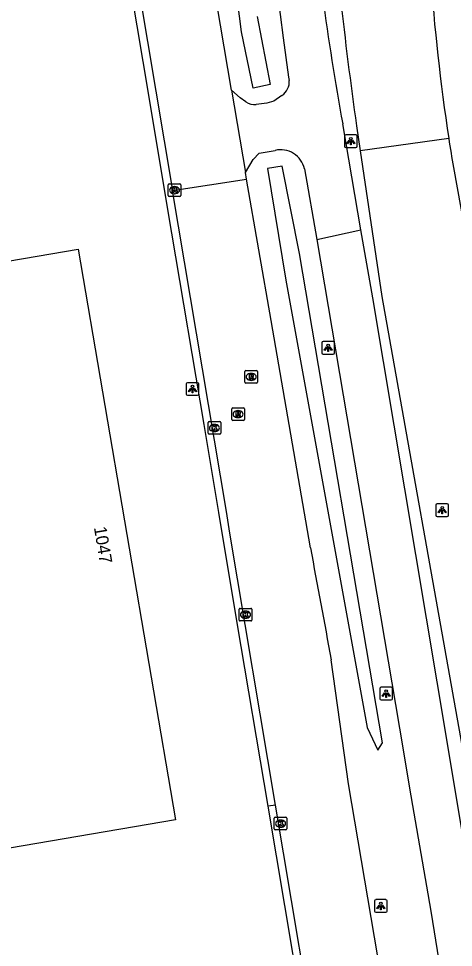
# Model space of a CAD drawing. Extents: x 154324 to 155743, y 382939 to 384183.
# Drawn here: x 154996.5 to 155031, y 383695.9 to 383769.7 of the extents above; entities that cross this region are included whole.
import ezdxf

# ---------------------------------------------------------------- set-up
doc = ezdxf.new("R2010")
doc.units = 0
for name, color, linetype in [('IMGEO_Fietspad_gesloten', 7, 'Continuous'), ('IMGEO_Kolk', 7, 'Continuous'), ('IMGEO_Lichtpunt', 7, 'Continuous'), ('IMGEO_Pand', 7, 'Continuous'), ('IMGEO_Pand_nummerreeks', 7, 'Continuous'), ('IMGEO_Rijbaan_lokaal_gesloten', 7, 'Continuous'), ('IMGEO_Rijbaan_lokaal_open', 7, 'Continuous'), ('IMGEO_Rijbaan_regionaal_gesloten', 7, 'Continuous'), ('IMGEO_Rioolput', 7, 'Continuous'), ('IMGEO_Waterloop', 7, 'Continuous')]:
    doc.layers.add(name, color=color, linetype=linetype)

msp = doc.modelspace()

# ---------------------------------------------------------------- linework, layer by layer
at = {"layer": 'IMGEO_Fietspad_gesloten'}
for points in [[(155016.997, 383771.855), (155017.48, 383768.134), (155017.908, 383765.009), (155017.961, 383764.734)], [(155014.521, 383763.048), (155014.065, 383763.349), (155013.373, 383763.974)], [(155017.375, 383763.556), (155016.736, 383763.085), (155016.191, 383762.943), (155015.337, 383762.826)], [(155023.65, 383752.887), (155022.201, 383761.283)], [(155014.481, 383757.434), (155015.084, 383758.454), (155015.579, 383758.975), (155016.83, 383759.18)], [(155019.156, 383757.716), (155020.155, 383752.117)], [(155020.155, 383752.117), (155023.65, 383752.887)], [(155069.375, 383489.212), (155067.803, 383490.288), (155064.93, 383506.848), (155055.586, 383562.322), (155035.787, 383680.446), (155030.556, 383711.937), (155024.582, 383747.491), (155023.65, 383752.887)], [(155020.155, 383752.117), (155027.003, 383711.594), (155027.513, 383708.543), (155029.197, 383698.769), (155030.596, 383690.066), (155052.123, 383561.719), (155057.1, 383532.805), (155064.796, 383488.095)]]:
    msp.add_lwpolyline(points, dxfattribs=at)
for centre, radius, start, end in [((155254.724, 383803.119), 236.257, 185.24892, 190.19973), ((155016.686, 383764.634), 1.279, 302.60576, 4.49784), ((155015.195, 383763.915), 1.098, 232.13028, 277.43079), ((155017.293, 383757.336), 1.902, 11.54173, 104.0851)]:
    msp.add_arc(centre, radius, start, end, dxfattribs=at)
at = {"layer": 'IMGEO_Kolk'}
for p, q in [((155008.354, 383755.604), (155008.354, 383756.456)), ((155008.429, 383756.53), (155009.281, 383756.53)), ((155008.842, 383756.31), (155008.867, 383756.31)), ((155009.355, 383756.456), (155009.355, 383755.604)), ((155009.281, 383755.53), (155008.429, 383755.53)), ((155008.865, 383755.75), (155008.84, 383755.75)), ((155011.514, 383736.723), (155011.514, 383737.575)), ((155011.589, 383737.649), (155012.441, 383737.649)), ((155012.515, 383737.575), (155012.515, 383736.723)), ((155012.025, 383736.869), (155012, 383736.869)), ((155012.002, 383737.429), (155012.027, 383737.429)), ((155012.441, 383736.649), (155011.589, 383736.649)), ((155014.061, 383722.823), (155014.913, 383722.823)), ((155013.986, 383721.897), (155013.986, 383722.749)), ((155014.474, 383722.603), (155014.499, 383722.603)), ((155014.987, 383722.749), (155014.987, 383721.897)), ((155014.913, 383721.823), (155014.061, 383721.823)), ((155014.497, 383722.043), (155014.472, 383722.043)), ((155016.771, 383705.306), (155016.771, 383706.158)), ((155016.846, 383706.232), (155017.698, 383706.232)), ((155017.259, 383706.012), (155017.284, 383706.012)), ((155017.772, 383706.158), (155017.772, 383705.306)), ((155017.698, 383705.232), (155016.846, 383705.232)), ((155017.282, 383705.452), (155017.257, 383705.452))]:
    msp.add_line(p, q, dxfattribs=at)
for points in [[(155008.354, 383755.604), (155008.354, 383756.456)], [(155008.429, 383756.53), (155009.281, 383756.53)], [(155008.675, 383756.23), (155008.798, 383756.23), (155008.798, 383756.079), (155008.928, 383756.23), (155009.092, 383756.23), (155008.946, 383756.079), (155009.099, 383755.83), (155008.947, 383755.83), (155008.862, 383755.994), (155008.798, 383755.927), (155008.798, 383755.83), (155008.675, 383755.83), (155008.675, 383756.23)], [(155009.355, 383756.456), (155009.355, 383755.604)], [(155009.281, 383755.53), (155008.429, 383755.53)], [(155011.514, 383736.723), (155011.514, 383737.575)], [(155011.589, 383737.649), (155012.441, 383737.649)], [(155012.515, 383737.575), (155012.515, 383736.723)], [(155011.835, 383737.349), (155011.958, 383737.349), (155011.958, 383737.198), (155012.088, 383737.349), (155012.252, 383737.349), (155012.106, 383737.198), (155012.259, 383736.949), (155012.107, 383736.949), (155012.022, 383737.113), (155011.958, 383737.046), (155011.958, 383736.949), (155011.835, 383736.949), (155011.835, 383737.349)], [(155012.441, 383736.649), (155011.589, 383736.649)], [(155014.061, 383722.823), (155014.913, 383722.823)], [(155013.986, 383721.897), (155013.986, 383722.749)], [(155014.307, 383722.523), (155014.43, 383722.523), (155014.43, 383722.372), (155014.56, 383722.523), (155014.724, 383722.523), (155014.578, 383722.372), (155014.731, 383722.123), (155014.579, 383722.123), (155014.494, 383722.287), (155014.43, 383722.22), (155014.43, 383722.123), (155014.307, 383722.123), (155014.307, 383722.523)], [(155014.987, 383722.749), (155014.987, 383721.897)], [(155014.913, 383721.823), (155014.061, 383721.823)], [(155016.771, 383705.306), (155016.771, 383706.158)], [(155016.846, 383706.232), (155017.698, 383706.232)], [(155017.092, 383705.932), (155017.215, 383705.932), (155017.215, 383705.781), (155017.345, 383705.932), (155017.509, 383705.932), (155017.363, 383705.781), (155017.516, 383705.532), (155017.364, 383705.532), (155017.279, 383705.696), (155017.215, 383705.629), (155017.215, 383705.532), (155017.092, 383705.532), (155017.092, 383705.932)], [(155017.772, 383706.158), (155017.772, 383705.306)], [(155017.698, 383705.232), (155016.846, 383705.232)]]:
    msp.add_lwpolyline(points, dxfattribs=at)
for centre, start, end in [((155008.431, 383756.454), 91.55205, 178.44795), ((155008.431, 383756.454), 91.55205, 178.44795), ((155009.279, 383756.454), 1.55205, 88.44795), ((155009.279, 383756.454), 1.55205, 88.44795), ((155008.431, 383755.606), 181.55205, 268.44795), ((155008.431, 383755.606), 181.55205, 268.44795), ((155009.279, 383755.606), 271.55205, 358.44795), ((155009.279, 383755.606), 271.55205, 358.44795), ((155011.591, 383737.573), 91.55205, 178.44795), ((155011.591, 383737.573), 91.55205, 178.44795), ((155012.439, 383737.573), 1.55205, 88.44795), ((155012.439, 383737.573), 1.55205, 88.44795), ((155011.591, 383736.725), 181.55205, 268.44795), ((155011.591, 383736.725), 181.55205, 268.44795), ((155012.439, 383736.725), 271.55205, 358.44795), ((155012.439, 383736.725), 271.55205, 358.44795), ((155014.063, 383722.747), 91.55205, 178.44795), ((155014.063, 383722.747), 91.55205, 178.44795), ((155014.911, 383722.747), 1.55205, 88.44795), ((155014.911, 383722.747), 1.55205, 88.44795), ((155014.063, 383721.899), 181.55205, 268.44795), ((155014.063, 383721.899), 181.55205, 268.44795), ((155014.911, 383721.899), 271.55205, 358.44795), ((155014.911, 383721.899), 271.55205, 358.44795), ((155016.848, 383706.156), 91.55205, 178.44795), ((155016.848, 383706.156), 91.55205, 178.44795), ((155017.696, 383706.156), 1.55205, 88.44795), ((155017.696, 383706.156), 1.55205, 88.44795), ((155016.848, 383705.308), 181.55205, 268.44795), ((155016.848, 383705.308), 181.55205, 268.44795), ((155017.696, 383705.308), 271.55205, 358.44795), ((155017.696, 383705.308), 271.55205, 358.44795)]:
    msp.add_arc(centre, 0.0765, start, end, dxfattribs=at)
for centre, major_axis, ratio, start_param, end_param in [((155008.841, 383756.03), (-0.387, 0.002), 0.722429, 4.712389, 7.853982), ((155008.866, 383756.03), (-0.39, 0.002), 0.717154, 1.570796, 4.712389), ((155012.001, 383737.149), (-0.387, 0.002), 0.722429, 4.712389, 7.853982), ((155012.026, 383737.149), (-0.39, 0.002), 0.717154, 1.570796, 4.712389), ((155014.473, 383722.323), (-0.387, 0.002), 0.722429, 4.712389, 7.853982), ((155014.498, 383722.323), (-0.39, 0.002), 0.717154, 1.570796, 4.712389), ((155017.258, 383705.732), (-0.387, 0.002), 0.722429, 4.712389, 7.853982), ((155017.283, 383705.732), (-0.39, 0.002), 0.717154, 1.570796, 4.712389)]:
    msp.add_ellipse(centre, major_axis=major_axis, ratio=ratio, start_param=start_param, end_param=end_param, dxfattribs=at)
at = {"layer": 'IMGEO_Lichtpunt'}
for p, q in [((155023.253, 383760.42), (155022.445, 383760.42)), ((155023.253, 383760.42), (155022.445, 383760.42)), ((155022.351, 383760.325), (155022.351, 383759.518)), ((155022.351, 383760.325), (155022.351, 383759.518)), ((155023.347, 383759.518), (155023.347, 383760.325)), ((155023.347, 383759.518), (155023.347, 383760.325)), ((155022.445, 383759.424), (155023.253, 383759.424)), ((155022.445, 383759.424), (155023.253, 383759.424)), ((155020.548, 383743.916), (155020.548, 383743.109)), ((155020.548, 383743.916), (155020.548, 383743.109)), ((155021.45, 383744.011), (155020.642, 383744.011)), ((155021.45, 383744.011), (155020.642, 383744.011)), ((155021.544, 383743.109), (155021.544, 383743.916)), ((155021.544, 383743.109), (155021.544, 383743.916)), ((155020.642, 383743.015), (155021.45, 383743.015)), ((155020.642, 383743.015), (155021.45, 383743.015)), ((155009.777, 383740.647), (155009.777, 383739.84)), ((155009.777, 383740.647), (155009.777, 383739.84)), ((155010.679, 383740.742), (155009.871, 383740.742)), ((155010.679, 383740.742), (155009.871, 383740.742)), ((155010.773, 383739.84), (155010.773, 383740.647)), ((155010.773, 383739.84), (155010.773, 383740.647)), ((155009.871, 383739.746), (155010.679, 383739.746)), ((155009.871, 383739.746), (155010.679, 383739.746)), ((155029.606, 383731.024), (155029.606, 383730.217)), ((155029.606, 383731.024), (155029.606, 383730.217)), ((155030.508, 383731.119), (155029.7, 383731.119)), ((155030.508, 383731.119), (155029.7, 383731.119)), ((155030.602, 383730.217), (155030.602, 383731.024)), ((155030.602, 383730.217), (155030.602, 383731.024)), ((155029.7, 383730.123), (155030.508, 383730.123)), ((155029.7, 383730.123), (155030.508, 383730.123)), ((155025.15, 383716.459), (155025.15, 383715.652)), ((155025.15, 383716.459), (155025.15, 383715.652)), ((155026.052, 383716.554), (155025.244, 383716.554)), ((155026.052, 383716.554), (155025.244, 383716.554)), ((155026.146, 383715.652), (155026.146, 383716.459)), ((155026.146, 383715.652), (155026.146, 383716.459)), ((155025.244, 383715.558), (155026.052, 383715.558)), ((155025.244, 383715.558), (155026.052, 383715.558)), ((155024.733, 383699.598), (155024.733, 383698.791)), ((155024.733, 383699.598), (155024.733, 383698.791)), ((155025.635, 383699.693), (155024.827, 383699.693)), ((155025.635, 383699.693), (155024.827, 383699.693)), ((155025.729, 383698.791), (155025.729, 383699.598)), ((155025.729, 383698.791), (155025.729, 383699.598)), ((155024.827, 383698.697), (155025.635, 383698.697)), ((155024.827, 383698.697), (155025.635, 383698.697))]:
    msp.add_line(p, q, dxfattribs=at)
for points in [[(155022.725, 383759.989), (155022.764, 383759.961), (155022.576, 383759.699), (155022.538, 383759.726), (155022.725, 383759.989)], [(155022.827, 383759.941), (155022.874, 383759.941), (155022.874, 383759.619), (155022.827, 383759.619), (155022.827, 383759.941)], [(155022.937, 383759.961), (155022.975, 383759.988), (155023.162, 383759.726), (155023.123, 383759.698), (155022.937, 383759.961)], [(155020.922, 383743.58), (155020.961, 383743.552), (155020.773, 383743.29), (155020.735, 383743.317), (155020.922, 383743.58)], [(155021.024, 383743.532), (155021.071, 383743.532), (155021.071, 383743.21), (155021.024, 383743.21), (155021.024, 383743.532)], [(155021.134, 383743.552), (155021.172, 383743.579), (155021.359, 383743.317), (155021.32, 383743.289), (155021.134, 383743.552)], [(155010.151, 383740.311), (155010.19, 383740.283), (155010.002, 383740.021), (155009.964, 383740.048), (155010.151, 383740.311)], [(155010.253, 383740.263), (155010.3, 383740.263), (155010.3, 383739.941), (155010.253, 383739.941), (155010.253, 383740.263)], [(155010.363, 383740.283), (155010.401, 383740.31), (155010.588, 383740.048), (155010.549, 383740.02), (155010.363, 383740.283)], [(155029.98, 383730.688), (155030.019, 383730.66), (155029.831, 383730.398), (155029.793, 383730.425), (155029.98, 383730.688)], [(155030.082, 383730.64), (155030.129, 383730.64), (155030.129, 383730.318), (155030.082, 383730.318), (155030.082, 383730.64)], [(155030.192, 383730.66), (155030.23, 383730.687), (155030.417, 383730.425), (155030.378, 383730.397), (155030.192, 383730.66)], [(155025.524, 383716.123), (155025.563, 383716.095), (155025.375, 383715.833), (155025.337, 383715.86), (155025.524, 383716.123)], [(155025.626, 383716.075), (155025.673, 383716.075), (155025.673, 383715.753), (155025.626, 383715.753), (155025.626, 383716.075)], [(155025.736, 383716.095), (155025.774, 383716.122), (155025.961, 383715.86), (155025.922, 383715.832), (155025.736, 383716.095)], [(155025.107, 383699.262), (155025.146, 383699.234), (155024.958, 383698.972), (155024.92, 383698.999), (155025.107, 383699.262)], [(155025.209, 383699.214), (155025.256, 383699.214), (155025.256, 383698.892), (155025.209, 383698.892), (155025.209, 383699.214)], [(155025.319, 383699.234), (155025.357, 383699.261), (155025.544, 383698.999), (155025.505, 383698.971), (155025.319, 383699.234)]]:
    msp.add_lwpolyline(points, dxfattribs=at)
for centre in [(155022.85, 383760.123), (155021.047, 383743.714), (155010.276, 383740.445), (155030.105, 383730.822), (155025.649, 383716.257), (155025.232, 383699.396)]:
    msp.add_circle(centre, 0.0994, dxfattribs=at)
for centre, start, end in [((155022.445, 383760.325), 90, 180), ((155022.445, 383760.325), 90, 180), ((155023.253, 383760.325), 0, 90), ((155023.253, 383760.325), 0, 90), ((155022.445, 383759.518), 180, 270), ((155022.445, 383759.518), 180, 270), ((155023.253, 383759.518), 270, 0), ((155023.253, 383759.518), 270, 360), ((155020.642, 383743.916), 90, 180), ((155020.642, 383743.916), 90, 180), ((155021.45, 383743.916), 0, 90), ((155021.45, 383743.916), 0, 90), ((155020.642, 383743.109), 180, 270), ((155020.642, 383743.109), 180, 270), ((155021.45, 383743.109), 270, 0), ((155021.45, 383743.109), 270, 360), ((155009.871, 383740.647), 90, 180), ((155009.871, 383740.647), 90, 180), ((155010.679, 383740.647), 0, 90), ((155010.679, 383740.647), 0, 90), ((155009.871, 383739.84), 180, 270), ((155009.871, 383739.84), 180, 270), ((155010.679, 383739.84), 270, 0), ((155010.679, 383739.84), 270, 360), ((155029.7, 383731.024), 90, 180), ((155029.7, 383731.024), 90, 180), ((155030.508, 383731.024), 0, 90), ((155030.508, 383731.024), 0, 90), ((155029.7, 383730.217), 180, 270), ((155029.7, 383730.217), 180, 270), ((155030.508, 383730.217), 270, 0), ((155030.508, 383730.217), 270, 360), ((155025.244, 383716.459), 90, 180), ((155025.244, 383716.459), 90, 180), ((155026.052, 383716.459), 0, 90), ((155026.052, 383716.459), 0, 90), ((155025.244, 383715.652), 180, 270), ((155025.244, 383715.652), 180, 270), ((155026.052, 383715.652), 270, 0), ((155026.052, 383715.652), 270, 360), ((155024.827, 383699.598), 90, 180), ((155024.827, 383699.598), 90, 180), ((155025.635, 383699.598), 0, 90), ((155025.635, 383699.598), 0, 90), ((155024.827, 383698.791), 180, 270), ((155024.827, 383698.791), 180, 270), ((155025.635, 383698.791), 270, 0), ((155025.635, 383698.791), 270, 360)]:
    msp.add_arc(centre, 0.0946, start, end, dxfattribs=at)
at = {"layer": 'IMGEO_Pand'}
msp.add_lwpolyline([(154944.892, 383741.692), (154944.883, 383741.744), (155001.211, 383751.343), (155008.926, 383706.026), (154952.606, 383696.427), (154952.596, 383696.484)], dxfattribs=at)
at = {"layer": 'IMGEO_Rijbaan_lokaal_gesloten'}
for points in [[(154990.18, 383866.132), (155008.692, 383756.004)], [(155013.373, 383763.974), (155010.136, 383783.072), (155010.285, 383783.102), (155007.976, 383797.016), (155002.174, 383831.432), (154996.943, 383862.793)], [(155013.373, 383763.974), (155014.481, 383757.434)], [(155008.692, 383756.004), (155014.572, 383756.911)], [(155014.572, 383756.911), (155014.481, 383757.434)], [(155019.641, 383727.625), (155016.525, 383745.686), (155014.572, 383756.911)], [(155016.871, 383707.197), (155013.247, 383728.802), (155012.973, 383730.527), (155008.692, 383756.004)], [(155059.928, 383487.45), (155052.477, 383531.831), (155025.49, 383692.18), (155022.669, 383708.88), (155021.296, 383718.742)], [(155059.439, 383453.463), (155046.503, 383530.572), (155016.871, 383707.197)]]:
    msp.add_lwpolyline(points, dxfattribs=at)
msp.add_arc((156385.943, 383977.586), 1388.979, 190.36746, 190.740192, dxfattribs=at)
at = {"layer": 'IMGEO_Rijbaan_lokaal_open'}
for points in [[(155016.277, 383707.107), (155013.835, 383721.664), (155012.365, 383730.431), (155011.19, 383737.428), (155008.641, 383752.609), (155006.354, 383766.232), (155002.093, 383791.612), (154997.464, 383819.179)], [(155016.871, 383707.197), (155016.277, 383707.107)], [(155065.709, 383396.485), (155065.341, 383401.33), (155064.659, 383408.986), (155063.139, 383423.564), (155063.03, 383424.403), (155061.613, 383435.27), (155060.487, 383443.041), (155058.846, 383453.397), (155045.918, 383530.449), (155024.164, 383660.104), (155016.277, 383707.107)]]:
    msp.add_lwpolyline(points, dxfattribs=at)
at = {"layer": 'IMGEO_Rijbaan_regionaal_gesloten'}
for points in [[(155023.296, 383761.147), (155023.592, 383759.163)], [(155030.623, 383760.14), (155023.592, 383759.163)], [(155023.592, 383759.163), (155025.319, 383747.582), (155031.523, 383712.699), (155040.998, 383657.511), (155047.66, 383620.638), (155058.726, 383558.566), (155063.68, 383530.41), (155070.593, 383489.047)], [(155030.993, 383757.82), (155045.927, 383675.069), (155050.278, 383650.736), (155055.096, 383623.794), (155056.54, 383616.113), (155069.465, 383544.367)]]:
    msp.add_lwpolyline(points, dxfattribs=at)
for centre, radius, start, end in [((155354.041, 383807.716), 334.007, 184.49728, 188.0146), ((155192.439, 383784.755), 163.677, 184.00415, 188.64952), ((155196.671, 383785.432), 167.963, 188.66067, 189.46208)]:
    msp.add_arc(centre, radius, start, end, dxfattribs=at)
at = {"layer": 'IMGEO_Rioolput'}
for p, q in [((155014.436, 383740.779), (155014.436, 383741.631)), ((155014.511, 383741.705), (155015.363, 383741.705)), ((155014.924, 383741.485), (155014.949, 383741.485)), ((155015.437, 383741.631), (155015.437, 383740.779)), ((155015.363, 383740.705), (155014.511, 383740.705)), ((155014.947, 383740.925), (155014.922, 383740.925)), ((155013.393, 383737.823), (155013.393, 383738.675)), ((155013.468, 383738.749), (155014.32, 383738.749)), ((155013.881, 383738.529), (155013.906, 383738.529)), ((155014.394, 383738.675), (155014.394, 383737.823)), ((155014.32, 383737.749), (155013.468, 383737.749)), ((155013.904, 383737.969), (155013.879, 383737.969))]:
    msp.add_line(p, q, dxfattribs=at)
for points in [[(155014.436, 383740.779), (155014.436, 383741.631)], [(155014.511, 383741.705), (155015.363, 383741.705)], [(155015.025, 383741.403), (155014.773, 383741.405), (155014.773, 383741.005)], [(155014.951, 383741.324), (155014.897, 383741.324), (155014.897, 383741.243)], [(155015.437, 383741.631), (155015.437, 383740.779)], [(155015.363, 383740.705), (155014.511, 383740.705)], [(155014.773, 383741.005), (155014.897, 383741.005), (155014.897, 383741.167), (155014.908, 383741.167)], [(155014.897, 383741.243), (155014.949, 383741.243)], [(155014.955, 383741.138), (155015.026, 383741.005), (155015.166, 383741.005), (155015.101, 383741.131)], [(155013.393, 383737.823), (155013.393, 383738.675)], [(155013.468, 383738.749), (155014.32, 383738.749)], [(155013.982, 383738.447), (155013.73, 383738.449), (155013.73, 383738.049)], [(155013.908, 383738.368), (155013.854, 383738.368), (155013.854, 383738.287)], [(155014.394, 383738.675), (155014.394, 383737.823)], [(155014.32, 383737.749), (155013.468, 383737.749)], [(155013.73, 383738.049), (155013.854, 383738.049), (155013.854, 383738.211), (155013.865, 383738.211)], [(155013.854, 383738.287), (155013.906, 383738.287)], [(155013.912, 383738.182), (155013.983, 383738.049), (155014.123, 383738.049), (155014.058, 383738.175)]]:
    msp.add_lwpolyline(points, dxfattribs=at)
for centre, radius, start, end in [((155014.513, 383741.629), 0.0765, 91.55205, 178.44795), ((155014.513, 383741.629), 0.0765, 91.55205, 178.44795), ((155014.933, 383741.432), 0.19, 274.7715, 282.96867), ((155014.957, 383741.228), 0.0964, 77.00612, 93.18647), ((155014.971, 383741.285), 0.0378, 276.66336, 79.67722), ((155015.024, 383741.293), 0.109, 350.36119, 89.41601), ((155015.022, 383741.293), 0.112, 277.58423, 350.98172), ((155015.361, 383741.629), 0.0765, 1.55205, 88.44795), ((155015.361, 383741.629), 0.0765, 1.55205, 88.44795), ((155014.513, 383740.781), 0.0765, 181.55205, 268.44795), ((155014.513, 383740.781), 0.0765, 181.55205, 268.44795), ((155014.907, 383741.114), 0.0533, 26.02933, 88.69889), ((155015.006, 383741.078), 0.108, 29.51342, 73.79051), ((155015.361, 383740.781), 0.0765, 271.55205, 358.44795), ((155015.361, 383740.781), 0.0765, 271.55205, 358.44795), ((155013.47, 383738.673), 0.0765, 91.55205, 178.44795), ((155013.47, 383738.673), 0.0765, 91.55205, 178.44795), ((155013.914, 383738.272), 0.0964, 77.00612, 93.18647), ((155013.928, 383738.329), 0.0378, 276.66336, 79.67722), ((155013.981, 383738.337), 0.109, 350.36119, 89.41601), ((155013.979, 383738.337), 0.112, 277.58423, 350.98172), ((155014.318, 383738.673), 0.0765, 1.55205, 88.44795), ((155014.318, 383738.673), 0.0765, 1.55205, 88.44795), ((155013.47, 383737.825), 0.0765, 181.55205, 268.44795), ((155013.47, 383737.825), 0.0765, 181.55205, 268.44795), ((155013.864, 383738.158), 0.0533, 26.02933, 88.69889), ((155013.89, 383738.476), 0.19, 274.7715, 282.96867), ((155013.963, 383738.122), 0.108, 29.51342, 73.79051), ((155014.318, 383737.825), 0.0765, 271.55205, 358.44795), ((155014.318, 383737.825), 0.0765, 271.55205, 358.44795)]:
    msp.add_arc(centre, radius, start, end, dxfattribs=at)
for centre, major_axis, ratio, start_param, end_param in [((155014.923, 383741.205), (-0.387, 0.002), 0.722429, 4.712389, 7.853982), ((155014.948, 383741.205), (-0.39, 0.002), 0.717154, 1.570796, 4.712389), ((155013.88, 383738.249), (-0.387, 0.002), 0.722429, 4.712389, 7.853982), ((155013.905, 383738.249), (-0.39, 0.002), 0.717154, 1.570796, 4.712389)]:
    msp.add_ellipse(centre, major_axis=major_axis, ratio=ratio, start_param=start_param, end_param=end_param, dxfattribs=at)
at = {"layer": 'IMGEO_Waterloop'}
for points in [[(155015.423, 383769.821), (155016.43, 383764.411), (155015.09, 383764.123), (155014.16, 383768.6), (155012.356, 383782.715)], [(155018.775, 383750.99), (155017.406, 383757.923), (155016.219, 383757.744), (155017.677, 383748.891), (155024.151, 383713.351), (155024.991, 383711.574), (155025.367, 383712.146), (155018.775, 383750.99)]]:
    msp.add_lwpolyline(points, dxfattribs=at)

# ---------------------------------------------------------------- texts
at = {"layer": 'IMGEO_Pand_nummerreeks'}
msp.add_text('1047', height=1, rotation=279.46505, dxfattribs=at).set_placement((155002.443, 383729.246))

doc.saveas('drawing.dxf')
